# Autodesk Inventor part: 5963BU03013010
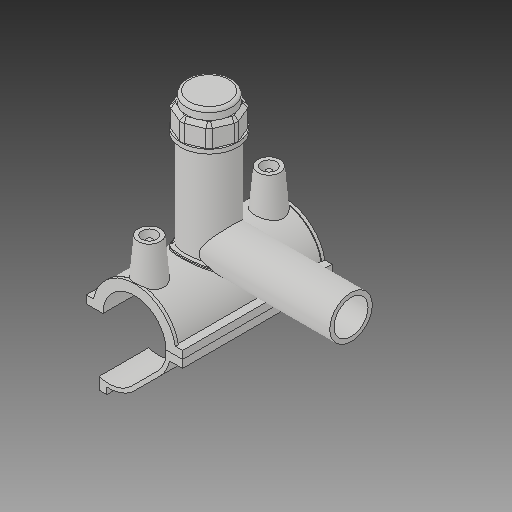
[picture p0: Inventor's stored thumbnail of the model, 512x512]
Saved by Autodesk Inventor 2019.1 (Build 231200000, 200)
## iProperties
Created: 2017-07
Part Number: 5963BU03013010
Material: Generic
Description: PLASSON TAPPING SADDLE 1 1/4''IPS x 1''CTS
Document SubType Name: Modeling
Designer: KIM
Mass: 1712.7 g
Surface Area: 2671.49 cm^2
Volume: 1712.7 cm^3
Density: 1 g/cm^3
Appearance: Default
Author: KIM
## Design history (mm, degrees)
derived "5963B.ipt"
feature "Solid1::5963B.ipt"
feature "Solid2::5963B.ipt"
feature "Solid4::5963B.ipt"
feature "Solid5::5963B.ipt"
tag "TaggingFeature1"
body "Solid1"
body "Solid2"
other parameters: "d_" = 42.1, "B_" = 64.516, "L_" = 100.076, "d_t" = 6, "H_2" = 93.726, "H_1" = 9.906, "d_1" = 28.45, "H_" = 94.996, "d1" = 54.73, "d148" = 0.6315, "d160" = 0.6315, "d169" = 3.2805, "d192" = 6.1236, "d0" = 42.1, "d2" = 64.516, "d3" = 10.525, "d4" = 100.076, "d5" = 0, "d6" = 0.1, "d8" = 0, "d19" = 6, "d20" = 6, "d21" = 60.0456, "d23" = 0, "d24" = 30.0228, "d26" = 0, "d29" = 3, "d30" = 14.03333, "d31" = 6, "d32" = 0, "d33" = 0, "d34" = 0.6, "d40" = 28.4596, "d41" = 37.89, "d43" = 0, "d45" = 0, "d47" = 87.4106, "d70" = 15, "d72" = 0, "d73" = 6, "d75" = 5, "d76" = 0, "d77" = 2.105, "d78" = 51.05, "d79" = 15, "d80" = 40.0304, "d82" = 5 deg, "d84" = 4, "d85" = 14, "d86" = 0, "d87" = 3, "d88" = 0, "d89" = 1, "d90" = 1, "d91" = 80.0608, "d92" = 0, "d93" = 0.5, "d94" = 22.15789, "d96" = 55.8246, "d97" = 2.00152, "d98" = 0, "d102" = 0.421, "d120" = 140 deg, "d121" = 24.228, "d122" = 20 deg, "d123" = 109.46, "d124" = 32.838, "d126" = 0, "d143" = 43.363, "d145" = 9.71538, "d149" = 0.6315, "d150" = 10.68692, "d153" = 100.076, "d154" = 0, "d156" = 27.365, "d157" = 160 deg, "d159" = 2.526, "d161" = 0.6315, "d162" = 60.0456, "d163" = 0, "d164" = 21.05, "d167" = 4.21, "d168" = 26.69756, "d170" = 3.2805, "d172" = 0, "d173" = 1, "d175" = 21.05, "d176" = 20 deg, "d177" = 2.947, "d178" = 12.63, "d180" = 0, "d183" = 5.052, "d184" = 2.3576, "d185" = 32.5247, "d186" = 32.5247, "d187" = 27.365, "d188" = 3.789, "d189" = 2.947, "d190" = 0, "d191" = 41.0475, "d193" = 6.1236, "d194" = 3.50266, "d195" = 90 deg, "d197" = 0, "d199" = 0, "d200" = 6.315, "d202" = 0, "d203" = 93.726, "d204" = 35.9955, "d205" = 26.523, "d206" = 32.2065, "d207" = 70.2945, "d208" = 73.10628, "d209" = 87.16518, "d210" = 32.5854, "d211" = 37.89, "d212" = 30.312, "d213" = -3.8871, "d216" = 0, "d217" = 4.21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
